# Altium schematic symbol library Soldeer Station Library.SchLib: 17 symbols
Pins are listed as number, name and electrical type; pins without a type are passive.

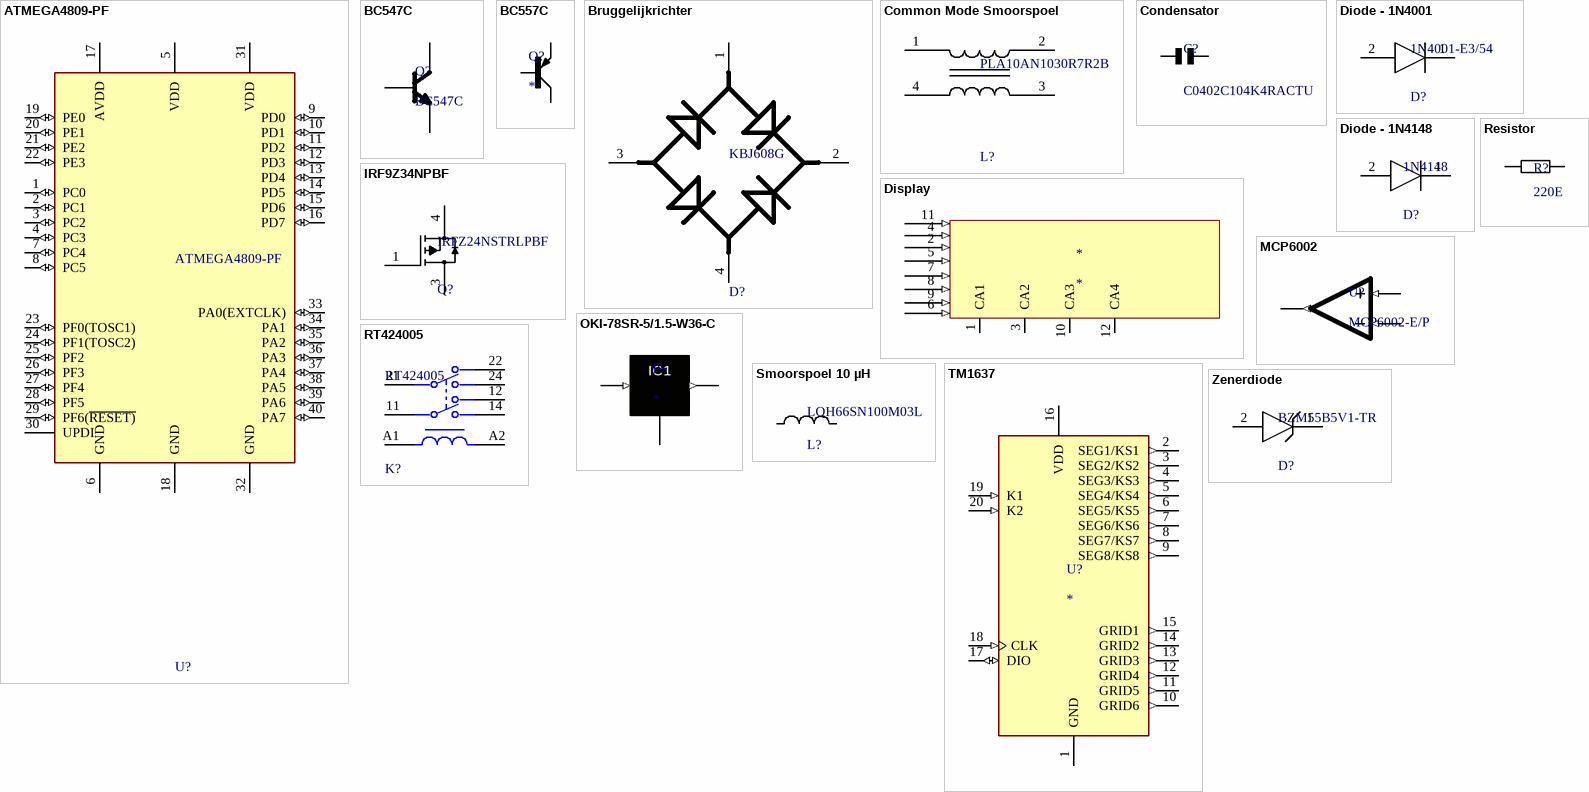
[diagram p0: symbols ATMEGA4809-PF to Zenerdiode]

## ATMEGA4809-PF
designator U?
footprint FP-C04-016-MFG
footprint ATmega4809-PF
pins: 1 PC0 (io), 2 PC1 (io), 3 PC2 (io), 4 PC3 (io), 5 VDD (power), 6 GND (power), 7 PC4 (io), 8 PC5 (io), 9 PD0 (io), 10 PD1 (io), 11 PD2 (io), 12 PD3 (io), 13 PD4 (io), 14 PD5 (io), 15 PD6 (io), 16 PD7 (io), 17 AVDD (power), 18 GND (power), 19 PE0 (io), 20 PE1 (io), 21 PE2 (io), 22 PE3 (io), 23 PF0(TOSC1) (io), 24 PF1(TOSC2) (io), 25 PF2 (io), 26 PF3 (io), 27 PF4 (io), 28 PF5 (io), 29 PF6(~{RESET)} (io), 30 UPDI, 31 VDD (power), 32 GND (power), 33 PA0(EXTCLK) (io), 34 PA1 (io), 35 PA2 (io), 36 PA3 (io), 37 PA4 (io), 38 PA5 (io), 39 PA6 (io), 40 PA7 (io)

## BC547C
designator Q?
Manufacturer: On Semiconductor; IC Continuous (A): 0.1; fT Min (MHz): 150; Packing: Bulk Box; Polarity: NPN
footprint ONSC-TO-92-3-29-11 (TO, 3-Leads, Body Dia 4.7mm, Pitch 1.27mm)
footprint SOT54A
footprint BC557C
pins: 1 C, 2 B, 3 E

## BC557C
designator Q?
MP: BC557; MF: ON
footprint SOT54A
footprint BC557C
pins: B, C, E

## Bruggelijkrichter
designator D?, comment KBJ608G
Manufacturer: Diodes; Max Junction Temp: +150°C; Max Surge Forward Current: 170A; Reverse Voltage: 800V; Peak Reverse Current: 5uA; Standoff Height: 3.3mm; Value: 80pF; Forward Current: 3A; Max Repetitive Reverse Voltage: 600V
footprint FP-KBJ-MFG
footprint D6KB6U - bruggelijk
pins: 1 +, 2 1 ~, 3 2 ~, 4 -

## Common Mode Smoorspoel
designator L?, comment PLA10AN1030R7R2B
Lead Diameter: 0.9mm; Voltage Rating (DC): 300V; Current: 700mA; Inductance: 10mH; Lead/Base Style: Pin; DC Resistance (DCR): 100mR; Shielding: Unshielded; Number of Lines: 2
footprint FP-PLA10A-PLH10A-MFG
footprint CM2545x171B-10
pins: 1, 2, 3, 4

## Condensator
designator C?, comment C0402C104K4RACTU
Manufacturer: Kemet
footprint CAPC1005X55X30ML05T10 (Chip Capacitor, 2-Leads, Body 1.00x0.50mm, IPC Low Density)
footprint CAPC1005X55X30LL05T10 (Chip Capacitor, 2-Leads, Body 1.00x0.50mm, IPC High Density)
footprint CAPC1005X55X30NL05T10 (Chip Capacitor, 2-Leads, Body 1.00x0.50mm, IPC Medium Density)
footprint Condensator
pins: 1, 2
1 alternate drawing of the same symbol

## Diode - 1N4001
designator D?, comment 1N4001-E3/54
Max Surge Current: 30A; Forward Voltage: 1.1V; Average Rectified Current: 1A; Voltage: 50V; Capacitance: 15pF; Peak Non-Repetitive Surge Current: 45A; Polarity: Standard; Max Reverse Current: 5uA; Element Configuration: Single
footprint FP-1N4001-E3-54-MFG
footprint 1N4007
pins: 1 C, 2 A

## Diode - 1N4148
designator D?, comment 1N4148
Reverse Voltage: 100V; Forward Voltage: 1V; Max Power Dissipation: 500mW; Average Rectified Current: 200mA; Max Reverse Current: 5uA; Forward Current: 300mA; Current: 4A; Reverse Recovery Time: 4ns; Element Configuration: Single; Outside Diameter: 1.85mm; Polarity: Standard; Max Forward Surge Current (Ifsm): 1A; Capacitance: 4pF
footprint FP-017AG-MFG
footprint 1N4148
pins: 1 C, 2 A

## Display
designator *
footprint DIP12
pins: 1 CA1, 2 (in), 3 CA2, 4 (in), 5 (in), 6 (in), 7 (in), 8 (in), 9 (in), 10 CA3, 11 (in), 12 CA4

## IRF9Z34NPBF
designator Q?, comment IRFZ24NSTRLPBF
Element Configuration: Single; Turn-On Delay Time: 4.9ns; Power Dissipation: 45W; Gate to Source Voltage (Vgs): 20V; Input Capacitance: 370pF; Max Dual Supply Voltage: 55V; Turn-Off Delay Time: 19ns; Max Power Dissipation: 3.8W; Continuous Drain Current (ID): 17A; Drain to Source Resistance: 70mR
footprint FP-PG-TO263-3-MFG
footprint IRF9Z34NPBF
pins: 1 GATE, 3 SOURCE, 4 DRAIN

## MCP6002
designator U?, comment MCP6002-E/P
IC2; Slew Rate: 0.6V/µs; Supply Current: 100uA; Power Supply Rejection Ratio (PSRR): 86dB; Input Offset Voltage (Vos): 4.5mV; Input Bias Current: 1pA; Amplifier Type: GENERAL PURPOSE; Unity Gain Bandwidth Product: 1MHz; Number of Circuits: 2; Output Current: 23mA; Operating Supply Voltage: 5.5V; Min Supply Voltage: 1.8V; Common Mode Rejection Ratio: 60dB; Voltage Gain: 112dB; Max Supply Voltage: 6V
footprint PDIP300-P8 (8-Pin Plastic Dual In-Line Package (PDIP))
footprint MCP6002
pins: 1 VOUTA (out), 2 VINA- (in), 3 VINA+ (in)

## OKI-78SR-5/1.5-W36-C
designator PS
MF: Murata Power; MP: OKI-78SR-5/1.5-W36-C
footprint CONV_OKI-78SR-5/1.5-W36-C
footprint OKI-78SR-5/1.5-W36-C
pins: 1 IN (in), 2 COM/GND (power), 3 OUT (out)

## Resistor
designator R?, comment 220E
Manufacturer: Vishay Dale; Part Number: CRCW08050000Z0EA
footprint Resistor (Chip Resistor, 2-Leads, Body 2,00x1,25mm, IPC Medium Density)
pins: 1, 2
1 alternate drawing of the same symbol

## RT424005
designator K?
Manufacturer: TE Connectivity; Coil Power: 403mW; Throw Configuration: DPDT; Coil Voltage: 5V; Number Of Contacts: 2; Coil Resistance: 62Ω; Current Rating: 8A; Coil Type: Non-Latching
footprint FP-RT424005-MFG
footprint RT424005
pins: 11, 12, 14, 21, 22, 24, A1, A2

## Smoorspoel 10 µH
designator L?, comment LQH66SN100M03L
Test Frequency: 1MHz; Max DC Current: 1.6A; Inductance Tolerance: 20%; Core Material: Ferrite; Self Resonant Frequency: 20MHz; DC Resistance (DCR): 36mR; Inductance: 10uH; Shielding: Shielded
footprint FP-LQH66SN_03-MFG
footprint Smoorspoel
pins: 1, 2

## TM1637
designator U?
MF: Titan Micro Electronics; MP: TM1637
footprint DIP778W43P254L2612H431Q20N
footprint TM1637
pins: 1 GND (power), 2 SEG1/KS1 (out), 3 SEG2/KS2 (out), 4 SEG3/KS3 (out), 5 SEG4/KS4 (out), 6 SEG5/KS5 (out), 7 SEG6/KS6 (out), 8 SEG7/KS7 (out), 9 SEG8/KS8 (out), 10 GRID6 (out), 11 GRID5 (out), 12 GRID4 (out), 13 GRID3 (out), 14 GRID2 (out), 15 GRID1 (out), 16 VDD (power), 17 DIO (io), 18 CLK (in), 19 K1 (in), 20 K2 (in)

## Zenerdiode
designator D?, comment BZM55B5V1-TR
Zener Voltage: 5.1V; Element Configuration: Single; Impedance: 60R; ESD Protection: No; Voltage Tolerance: 2%; Power Dissipation: 500mW; Max Reverse Leakage Current: 100nA; Test Current: 5mA
footprint FP-6_560-5007_01-4-MFG
footprint Zenerdiode
pins: 1 C, 2 A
